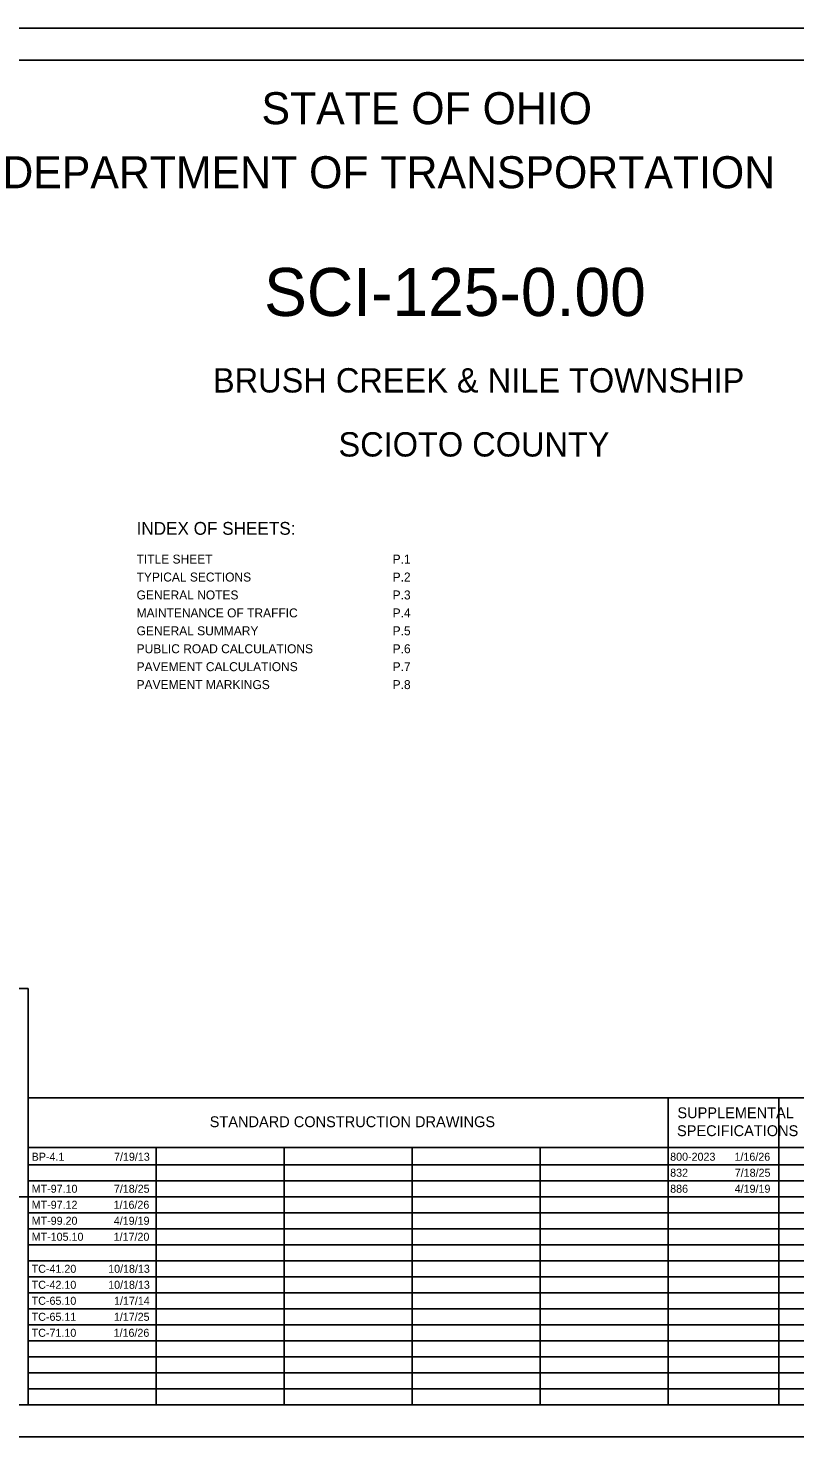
# Model space of a CAD drawing. Extents: x 0 to 34, y 0 to 22.
# Drawn here: x 10.15 to 22.13, y 0 to 22 of the extents above; entities that cross this region are included whole.
import ezdxf

# ---------------------------------------------------------------- set-up
doc = ezdxf.new("R2010")
doc.units = 0
for name, color, linetype in [('Default', 7, 'Continuous'), ('SH_Border', 7, 'Continuous'), ('SH_Cut_Line', 7, 'Continuous'), ('SH_Data', 7, 'Continuous'), ('SH_Text', 7, 'Continuous')]:
    doc.layers.add(name, color=color, linetype=linetype)

msp = doc.modelspace()

# ---------------------------------------------------------------- linework, layer by layer
at = {"layer": 'SH_Border'}
msp.add_lwpolyline([(1.5, 21.5), (33.5, 21.5), (33.5, 0.5), (1.5, 0.5)], close=True, dxfattribs=at)
at = {"layer": 'SH_Cut_Line'}
msp.add_lwpolyline([(0, 0), (34, 0), (34, 22), (0, 22)], close=True, dxfattribs=at)
at = {"layer": 'SH_Data'}
for p, q in [((10.15, 5.292), (23.6, 5.292)), ((10.15, 0.5), (10.15, 5.292)), ((20.15, 0.5), (20.15, 5.292)), ((21.875, 0.5), (21.875, 5.292)), ((10.15, 4.521), (23.6, 4.521)), ((12.15, 0.5), (12.15, 4.521)), ((14.15, 0.5), (14.15, 4.521)), ((16.15, 0.5), (16.15, 4.521)), ((18.15, 0.5), (18.15, 4.521)), ((10.15, 4.25), (23.6, 4.25)), ((10.15, 4), (23.6, 4)), ((10.15, 3.75), (23.6, 3.75)), ((10.15, 3.5), (23.6, 3.5)), ((10.15, 3.25), (23.6, 3.25)), ((10.15, 3), (23.6, 3)), ((10.15, 2.75), (23.6, 2.75)), ((10.15, 2.5), (23.6, 2.5)), ((10.15, 2.25), (23.6, 2.25)), ((10.15, 2), (23.6, 2)), ((10.15, 1.75), (23.6, 1.75)), ((10.15, 1.5), (23.6, 1.5)), ((10.15, 1.25), (23.6, 1.25)), ((10.15, 1), (23.6, 1)), ((10.15, 0.75), (23.6, 0.75))]:
    msp.add_line(p, q, dxfattribs=at)
for points in [[(10.15, 7), (7.35, 7), (7.35, 3.75), (10.15, 3.75)], [(10.15, 3.75), (7.35, 3.75), (7.35, 0.5), (10.15, 0.5)]]:
    msp.add_lwpolyline(points, close=True, dxfattribs=at)

# ---------------------------------------------------------------- texts
at = {"layer": 'Default'}
for s, p in [('BP-4.1', (10.205, 4.312)), ('7/19/13', (11.492, 4.312)), ('800-2023', (20.18, 4.312)), ('1/16/26', (21.185, 4.312)), ('832', (20.18, 4.062)), ('7/18/25', (21.189, 4.062)), ('MT-97.10', (10.205, 3.812)), ('7/18/25', (11.489, 3.812)), ('886', (20.18, 3.812)), ('4/19/19', (21.188, 3.812)), ('MT-97.12', (10.205, 3.562)), ('1/16/26', (11.485, 3.562)), ('MT-99.20', (10.205, 3.312)), ('4/19/19', (11.488, 3.312)), ('MT-105.10', (10.205, 3.062)), ('1/17/20', (11.486, 3.062)), ('TC-41.20', (10.205, 2.562)), ('10/18/13', (11.4, 2.562)), ('TC-42.10', (10.205, 2.312)), ('10/18/13', (11.4, 2.312)), ('TC-65.10', (10.205, 2.062)), ('1/17/14', (11.492, 2.062)), ('TC-65.11', (10.205, 1.812)), ('1/17/25', (11.489, 1.812)), ('TC-71.10', (10.205, 1.562)), ('1/16/26', (11.485, 1.562))]:
    msp.add_text(s, height=0.125, dxfattribs=at).set_placement(p)
at = {"layer": 'SH_Text'}
for s, height, p in [('STATE OF OHIO', 0.5, (13.795, 20.5)), ('DEPARTMENT OF TRANSPORTATION', 0.5, (9.747, 19.5)), ('SCI-125-0.00', 0.75, (13.835, 17.505)), ('BRUSH CREEK & NILE TOWNSHIP', 0.38, (13.037, 16.31)), ('SCIOTO COUNTY', 0.38, (14.998, 15.31)), ('INDEX OF SHEETS:', 0.2, (11.844, 14.088)), ('TITLE SHEET', 0.14, (11.844, 13.638)), ('P.1', 0.14, (15.844, 13.638)), ('TYPICAL SECTIONS', 0.14, (11.844, 13.358)), ('P.2', 0.14, (15.844, 13.358)), ('GENERAL NOTES', 0.14, (11.844, 13.078)), ('P.3', 0.14, (15.844, 13.078)), ('MAINTENANCE OF TRAFFIC', 0.14, (11.844, 12.798)), ('P.4', 0.14, (15.844, 12.798)), ('GENERAL SUMMARY', 0.14, (11.844, 12.518)), ('P.5', 0.14, (15.844, 12.518)), ('PUBLIC ROAD CALCULATIONS', 0.14, (11.844, 12.238)), ('P.6', 0.14, (15.844, 12.238)), ('PAVEMENT CALCULATIONS', 0.14, (11.844, 11.958)), ('P.7', 0.14, (15.844, 11.958)), ('PAVEMENT MARKINGS', 0.14, (11.844, 11.678)), ('P.8', 0.14, (15.844, 11.678)), ('SUPPLEMENTAL', 0.17, (20.293, 4.976)), ('STANDARD CONSTRUCTION DRAWINGS', 0.17, (12.986, 4.836)), ('SPECIFICATIONS', 0.17, (20.287, 4.696))]:
    msp.add_text(s, height=height, dxfattribs=at).set_placement(p)

doc.saveas('drawing.dxf')
